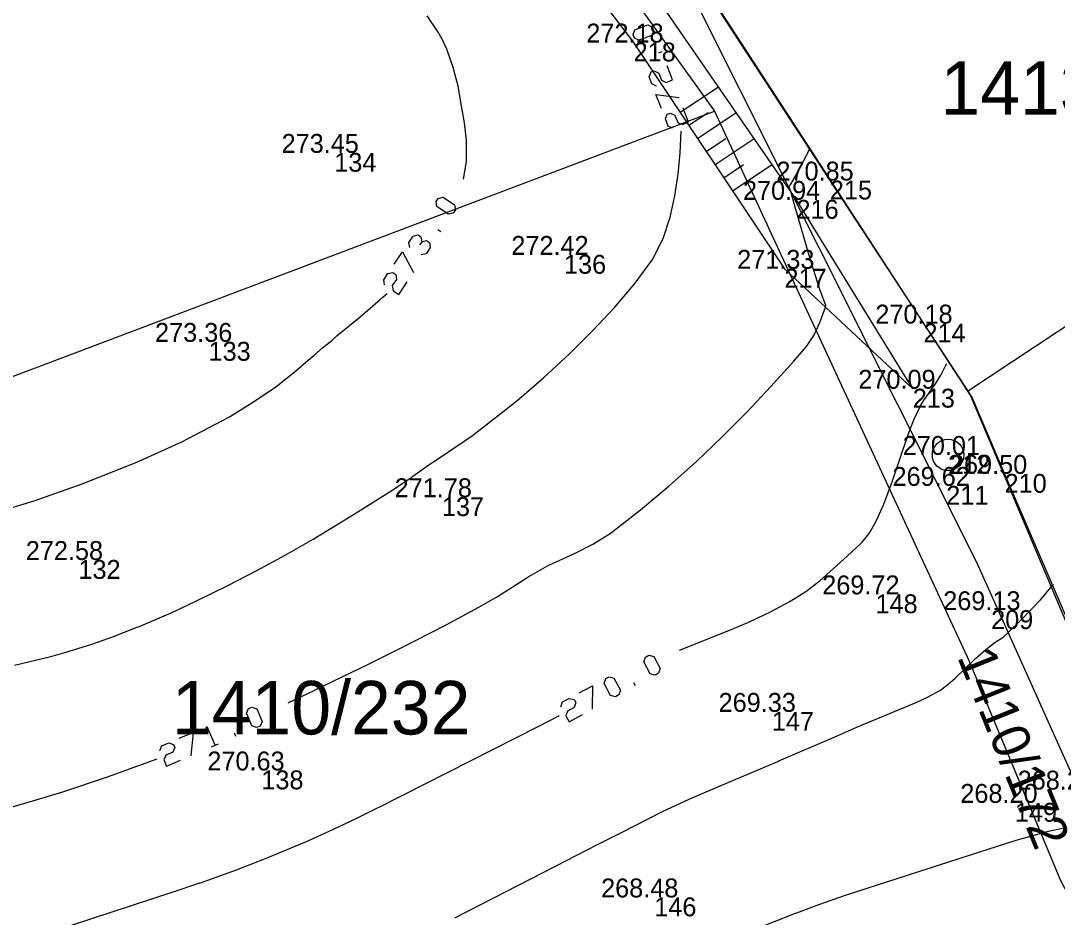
# Model space of a CAD drawing. Extents: x -771260 to -770828, y -1053564 to -1052811.
# Drawn here: x -770951.08 to -770918.15, y -1053293.16 to -1053264.67 of the extents above; entities that cross this region are included whole.
import ezdxf

# ---------------------------------------------------------------- set-up
doc = ezdxf.new("R2010")
doc.units = 0
for name, color, linetype in [('18_8_2023_plot', 7, 'Continuous'), ('18_8_2023_sachta', 7, 'Continuous'), ('18_8_2023_ter_hrana', 7, 'Continuous'), ('18_8_2023_ter_pata', 7, 'Continuous'), ('18_8_2023_ter_srafa', 7, 'Continuous'), ('18_8_2023_vrstevnice_po_1m', 7, 'Continuous'), ('18_8_2023_zamereny_bod', 7, 'Continuous'), ('18_8_2023_zamereny_bod_cislo', 7, 'Continuous'), ('18_8_2023_zamereny_bod_vyska', 7, 'Continuous'), ('DKM_Hranice parcel', 7, 'Continuous'), ('DKM_Parcelní čísla', 7, 'Continuous')]:
    doc.layers.add(name, color=color, linetype=linetype)

msp = doc.modelspace()

# ---------------------------------------------------------------- linework, layer by layer
at = {"layer": '18_8_2023_plot'}
for p, q in [((-770929.672, -1053263.164), (-770925.377, -1053269.752)), ((-770925.377, -1053269.752), (-770920.87, -1053276.639)), ((-770920.87, -1053276.639), (-770919.828, -1053279.071)), ((-770919.828, -1053279.071), (-770914.484, -1053291.532))]:
    msp.add_line(p, q, dxfattribs=at)
at = {"layer": '18_8_2023_sachta'}
msp.add_circle((-770921.622, -1053278.469), 0.5, dxfattribs=at)
at = {"layer": '18_8_2023_ter_hrana'}
for p, q in [((-770938.594, -1053256.22), (-770931.61, -1053265.367)), ((-770931.61, -1053265.367), (-770926.819, -1053272.556)), ((-770926.819, -1053272.556), (-770922.744, -1053276.366))]:
    msp.add_line(p, q, dxfattribs=at)
at = {"layer": '18_8_2023_ter_pata'}
for p, q in [((-770926.437, -1053270.365), (-770930.841, -1053263.982)), ((-770922.744, -1053276.366), (-770926.437, -1053270.365))]:
    msp.add_line(p, q, dxfattribs=at)
at = {"layer": '18_8_2023_ter_srafa'}
for p, q in [((-770930.134, -1053267.581), (-770928.917, -1053266.77)), ((-770929.856, -1053267.997), (-770929.244, -1053267.589)), ((-770929.579, -1053268.413), (-770928.349, -1053267.593)), ((-770929.302, -1053268.829), (-770928.683, -1053268.417)), ((-770929.025, -1053269.245), (-770927.781, -1053268.416)), ((-770928.747, -1053269.661), (-770928.122, -1053269.245)), ((-770928.47, -1053270.078), (-770927.213, -1053269.24))]:
    msp.add_line(p, q, dxfattribs=at)
at = {"layer": '18_8_2023_vrstevnice_po_1m'}
for points in [[(-770937.013, -1053269.71), (-770936.921, -1053269.144), (-770936.917, -1053268.488), (-770936.925, -1053268.37), (-770936.981, -1053267.919), (-770937.075, -1053267.382), (-770937.186, -1053266.751), (-770937.34, -1053266.158), (-770937.543, -1053265.582), (-770937.683, -1053265.278), (-770937.818, -1053265.034), (-770938.172, -1053264.514)], [(-770930.975, -1053264.991), (-770931.034, -1053265.142), (-770931.441, -1053265.297), (-770931.585, -1053265.224), (-770931.628, -1053265.113), (-770931.569, -1053264.962), (-770931.162, -1053264.806), (-770931.018, -1053264.879), (-770930.975, -1053264.991)], [(-770937.818, -1053265.034), (-770937.818, -1053265.034)], [(-770937.683, -1053265.278), (-770937.683, -1053265.278)], [(-770937.543, -1053265.582), (-770937.543, -1053265.582)], [(-770930.718, -1053265.662), (-770930.82, -1053265.701)], [(-770937.34, -1053266.158), (-770937.34, -1053266.158)], [(-770930.884, -1053266.751), (-770931.029, -1053266.678), (-770931.114, -1053266.454), (-770931.055, -1053266.303), (-770930.954, -1053266.265), (-770930.809, -1053266.337), (-770930.724, -1053266.561), (-770930.579, -1053266.634), (-770930.376, -1053266.556), (-770930.547, -1053266.109)], [(-770937.186, -1053266.751), (-770937.186, -1053266.751)], [(-770930.729, -1053267.46), (-770930.9, -1053267.013), (-770930.162, -1053267.115)], [(-770930.371, -1053268.092), (-770930.515, -1053268.019), (-770930.601, -1053267.796), (-770930.542, -1053267.645), (-770930.44, -1053267.606), (-770930.296, -1053267.679), (-770930.21, -1053267.903), (-770930.066, -1053267.976), (-770929.862, -1053267.898), (-770930.034, -1053267.451)], [(-770951.278, -1053285.145), (-770950.122, -1053284.874), (-770949.677, -1053284.747), (-770948.817, -1053284.481), (-770948.1, -1053284.224), (-770947.386, -1053283.946), (-770947.341, -1053283.929), (-770946.229, -1053283.45), (-770945.427, -1053283.075), (-770944.496, -1053282.619), (-770943.581, -1053282.143), (-770942.681, -1053281.652), (-770941.793, -1053281.144), (-770940.921, -1053280.62), (-770940.369, -1053280.273), (-770939.345, -1053279.631), (-770938.657, -1053279.174), (-770938.618, -1053279.147), (-770938.036, -1053278.734), (-770938.002, -1053278.71), (-770936.964, -1053278.013), (-770936.699, -1053277.827), (-770936.677, -1053277.811), (-770936.246, -1053277.486), (-770935.32, -1053276.75), (-770934.464, -1053276.01), (-770933.661, -1053275.266), (-770932.906, -1053274.52), (-770932.205, -1053273.77), (-770931.564, -1053273.016), (-770931.035, -1053272.289), (-770931.011, -1053272.256), (-770930.674, -1053271.589), (-770930.45, -1053270.915), (-770930.298, -1053270.236), (-770930.197, -1053269.553), (-770930.135, -1053268.869), (-770930.103, -1053268.182)], [(-770936.981, -1053267.919), (-770936.981, -1053267.919)], [(-770936.925, -1053268.37), (-770936.925, -1053268.37)], [(-770936.917, -1053268.488), (-770936.917, -1053268.488)], [(-770942.585, -1053286.346), (-770941.758, -1053285.955), (-770941.744, -1053285.948), (-770940.011, -1053285.109), (-770939.015, -1053284.612), (-770937.568, -1053283.867), (-770936.527, -1053283.309), (-770936.004, -1053283.008), (-770935.967, -1053282.987), (-770934.942, -1053282.332), (-770934.344, -1053281.995), (-770934.301, -1053281.971), (-770933.507, -1053281.607), (-770932.887, -1053281.298), (-770932.405, -1053280.999), (-770932.359, -1053280.97), (-770931.387, -1053280.218), (-770930.479, -1053279.452), (-770929.618, -1053278.676), (-770928.796, -1053277.89), (-770928.007, -1053277.098), (-770927.249, -1053276.298), (-770926.519, -1053275.492), (-770926.127, -1053275.032), (-770926.097, -1053274.997), (-770925.886, -1053274.674), (-770925.7, -1053274.263), (-770925.52, -1053273.771), (-770925.503, -1053273.725), (-770925.712, -1053273.148), (-770926.006, -1053272.235), (-770926.478, -1053270.598), (-770926.586, -1053270.221), (-770926.611, -1053270.134), (-770926.624, -1053270.093), (-770926.672, -1053269.947), (-770926.644, -1053269.905), (-770926.616, -1053269.865), (-770926.389, -1053269.463), (-770926.023, -1053268.761), (-770926, -1053268.717)], [(-770930.135, -1053268.869), (-770930.135, -1053268.869)], [(-770926, -1053268.717), (-770926, -1053268.717)], [(-770926, -1053268.717), (-770926, -1053268.717)], [(-770936.921, -1053269.144), (-770936.921, -1053269.144)], [(-770930.197, -1053269.553), (-770930.197, -1053269.553)], [(-770926.389, -1053269.463), (-770926.389, -1053269.463)], [(-770937.013, -1053269.71), (-770937.013, -1053269.71)], [(-770926.616, -1053269.865), (-770926.616, -1053269.865)], [(-770926.672, -1053269.947), (-770926.672, -1053269.947)], [(-770926.611, -1053270.134), (-770926.611, -1053270.134)], [(-770937.339, -1053270.784), (-770937.496, -1053270.823), (-770937.858, -1053270.581), (-770937.882, -1053270.421), (-770937.815, -1053270.322), (-770937.658, -1053270.283), (-770937.296, -1053270.525), (-770937.272, -1053270.685), (-770937.339, -1053270.784)], [(-770930.298, -1053270.236), (-770930.298, -1053270.236)], [(-770930.45, -1053270.915), (-770930.45, -1053270.915)], [(-770938.723, -1053271.875), (-770938.747, -1053271.715), (-770938.614, -1053271.516), (-770938.457, -1053271.477), (-770938.366, -1053271.538), (-770938.342, -1053271.698)], [(-770937.738, -1053271.382), (-770937.829, -1053271.321)], [(-770938.342, -1053271.698), (-770938.409, -1053271.797)], [(-770938.342, -1053271.698), (-770938.185, -1053271.659), (-770938.095, -1053271.719), (-770938.071, -1053271.879), (-770938.204, -1053272.078), (-770938.361, -1053272.117)], [(-770930.674, -1053271.589), (-770930.674, -1053271.589)], [(-770939.213, -1053272.412), (-770938.946, -1053272.014), (-770938.603, -1053272.675)], [(-770931.011, -1053272.256), (-770931.011, -1053272.256)], [(-770926.006, -1053272.235), (-770926.006, -1053272.235)], [(-770939.521, -1053273.07), (-770939.545, -1053272.91), (-770939.412, -1053272.71), (-770939.255, -1053272.671), (-770939.165, -1053272.732), (-770939.141, -1053272.892), (-770939.274, -1053273.091), (-770939.25, -1053273.251), (-770939.069, -1053273.372), (-770938.803, -1053272.974)], [(-770931.564, -1053273.016), (-770931.564, -1053273.016)], [(-770925.712, -1053273.148), (-770925.712, -1053273.148)], [(-770951.665, -1053280.24), (-770950.647, -1053279.926), (-770949.13, -1053279.385), (-770947.388, -1053278.695), (-770947.373, -1053278.689), (-770945.956, -1053278.05), (-770944.448, -1053277.257), (-770943.648, -1053276.766), (-770942.969, -1053276.303), (-770942.929, -1053276.276), (-770942.342, -1053275.801), (-770941.952, -1053275.463), (-770941.771, -1053275.315), (-770941.489, -1053275.068), (-770941.197, -1053274.831), (-770941.024, -1053274.678), (-770940.293, -1053274.078), (-770939.664, -1053273.526), (-770939.632, -1053273.498), (-770939.44, -1053273.34)], [(-770939.632, -1053273.498), (-770939.632, -1053273.498)], [(-770932.205, -1053273.77), (-770932.205, -1053273.77)], [(-770925.503, -1053273.725), (-770925.503, -1053273.725)], [(-770940.293, -1053274.078), (-770940.293, -1053274.078)], [(-770925.7, -1053274.263), (-770925.7, -1053274.263)], [(-770941.024, -1053274.678), (-770941.024, -1053274.678)], [(-770932.906, -1053274.52), (-770932.906, -1053274.52)], [(-770925.886, -1053274.674), (-770925.886, -1053274.674)], [(-770941.489, -1053275.068), (-770941.489, -1053275.068)], [(-770941.197, -1053274.831), (-770941.197, -1053274.831)], [(-770926.097, -1053274.997), (-770926.097, -1053274.997)], [(-770941.952, -1053275.463), (-770941.952, -1053275.463)], [(-770941.771, -1053275.315), (-770941.771, -1053275.315)], [(-770933.661, -1053275.266), (-770933.661, -1053275.266)], [(-770942.342, -1053275.801), (-770942.342, -1053275.801)], [(-770930.149, -1053284.673), (-770928.475, -1053284), (-770927.904, -1053283.757), (-770927.259, -1053283.454), (-770926.668, -1053283.139), (-770926.142, -1053282.81), (-770925.732, -1053282.495), (-770925.692, -1053282.464), (-770924.832, -1053281.687), (-770924.383, -1053281.271), (-770924.351, -1053281.241), (-770924.127, -1053280.966), (-770923.903, -1053280.569), (-770923.662, -1053280.03), (-770923.39, -1053279.295), (-770923.144, -1053278.571), (-770922.888, -1053277.82), (-770922.706, -1053277.349), (-770922.533, -1053276.976), (-770922.509, -1053276.923), (-770922.381, -1053276.722), (-770922.373, -1053276.711), (-770922.02, -1053276.207), (-770921.852, -1053275.94), (-770921.689, -1053275.621), (-770921.666, -1053275.575)], [(-770926.519, -1053275.492), (-770926.519, -1053275.492)], [(-770921.666, -1053275.575), (-770921.666, -1053275.575)], [(-770921.666, -1053275.575), (-770921.666, -1053275.575)], [(-770934.464, -1053276.01), (-770934.464, -1053276.01)], [(-770921.852, -1053275.94), (-770921.852, -1053275.94)], [(-770942.929, -1053276.276), (-770942.929, -1053276.276)], [(-770927.249, -1053276.298), (-770927.249, -1053276.298)], [(-770922.02, -1053276.207), (-770922.02, -1053276.207)], [(-770943.648, -1053276.766), (-770943.648, -1053276.766)], [(-770935.32, -1053276.75), (-770935.32, -1053276.75)], [(-770922.381, -1053276.722), (-770922.381, -1053276.722)], [(-770928.007, -1053277.098), (-770928.007, -1053277.098)], [(-770922.509, -1053276.923), (-770922.509, -1053276.923)], [(-770944.448, -1053277.257), (-770944.448, -1053277.257)], [(-770922.706, -1053277.349), (-770922.706, -1053277.349)], [(-770936.246, -1053277.486), (-770936.246, -1053277.486)], [(-770945.956, -1053278.05), (-770945.956, -1053278.05)], [(-770936.964, -1053278.013), (-770936.964, -1053278.013)], [(-770936.677, -1053277.811), (-770936.677, -1053277.811)], [(-770928.796, -1053277.89), (-770928.796, -1053277.89)], [(-770922.888, -1053277.82), (-770922.888, -1053277.82)], [(-770947.373, -1053278.689), (-770947.373, -1053278.689)], [(-770938.002, -1053278.71), (-770938.002, -1053278.71)], [(-770929.618, -1053278.676), (-770929.618, -1053278.676)], [(-770949.13, -1053279.385), (-770949.13, -1053279.385)], [(-770938.618, -1053279.147), (-770938.618, -1053279.147)], [(-770923.39, -1053279.295), (-770923.39, -1053279.295)], [(-770939.345, -1053279.631), (-770939.345, -1053279.631)], [(-770930.479, -1053279.452), (-770930.479, -1053279.452)], [(-770950.647, -1053279.926), (-770950.647, -1053279.926)], [(-770923.662, -1053280.03), (-770923.662, -1053280.03)], [(-770931.387, -1053280.218), (-770931.387, -1053280.218)], [(-770940.921, -1053280.62), (-770940.921, -1053280.62)], [(-770923.903, -1053280.569), (-770923.903, -1053280.569)], [(-770932.359, -1053280.97), (-770932.359, -1053280.97)], [(-770924.127, -1053280.966), (-770924.127, -1053280.966)], [(-770941.793, -1053281.144), (-770941.793, -1053281.144)], [(-770932.887, -1053281.298), (-770932.887, -1053281.298)], [(-770924.351, -1053281.241), (-770924.351, -1053281.241)], [(-770942.681, -1053281.652), (-770942.681, -1053281.652)], [(-770933.507, -1053281.607), (-770933.507, -1053281.607)], [(-770924.832, -1053281.687), (-770924.832, -1053281.687)], [(-770934.301, -1053281.971), (-770934.301, -1053281.971)], [(-770943.581, -1053282.143), (-770943.581, -1053282.143)], [(-770934.942, -1053282.332), (-770934.942, -1053282.332)], [(-770944.496, -1053282.619), (-770944.496, -1053282.619)], [(-770937.285, -1053293.181), (-770934.067, -1053291.521), (-770932.761, -1053290.847), (-770932.037, -1053290.488), (-770931.999, -1053290.469), (-770930.698, -1053289.802), (-770929.821, -1053289.4), (-770928.658, -1053288.901), (-770927.034, -1053288.205), (-770927.001, -1053288.191), (-770925.17, -1053287.4), (-770924.5, -1053287.11), (-770922.618, -1053286.325), (-770922.272, -1053286.164), (-770921.888, -1053285.952), (-770921.849, -1053285.931), (-770921.625, -1053285.768), (-770921.398, -1053285.566), (-770920.753, -1053284.942), (-770920.427, -1053284.652), (-770920.13, -1053284.419), (-770920.098, -1053284.394), (-770919.992, -1053284.334), (-770919.876, -1053284.256), (-770919.841, -1053284.232), (-770919.736, -1053284.132), (-770919.286, -1053283.703), (-770918.687, -1053283.069), (-770918.305, -1053282.622), (-770918.275, -1053282.586)], [(-770925.692, -1053282.464), (-770925.692, -1053282.464)], [(-770935.967, -1053282.987), (-770935.967, -1053282.987)], [(-770926.142, -1053282.81), (-770926.142, -1053282.81)], [(-770945.427, -1053283.075), (-770945.427, -1053283.075)], [(-770936.527, -1053283.309), (-770936.527, -1053283.309)], [(-770926.668, -1053283.139), (-770926.668, -1053283.139)], [(-770918.687, -1053283.069), (-770918.687, -1053283.069)], [(-770946.229, -1053283.45), (-770946.229, -1053283.45)], [(-770927.259, -1053283.454), (-770927.259, -1053283.454)], [(-770919.286, -1053283.703), (-770919.286, -1053283.703)], [(-770947.341, -1053283.929), (-770947.341, -1053283.929)], [(-770937.568, -1053283.867), (-770937.568, -1053283.867)], [(-770928.475, -1053284), (-770928.475, -1053284)], [(-770927.904, -1053283.757), (-770927.904, -1053283.757)], [(-770948.1, -1053284.224), (-770948.1, -1053284.224)], [(-770919.992, -1053284.334), (-770919.992, -1053284.334)], [(-770919.841, -1053284.232), (-770919.841, -1053284.232)], [(-770948.817, -1053284.481), (-770948.817, -1053284.481)], [(-770939.015, -1053284.612), (-770939.015, -1053284.612)], [(-770930.149, -1053284.673), (-770930.149, -1053284.673)], [(-770920.427, -1053284.652), (-770920.427, -1053284.652)], [(-770920.098, -1053284.394), (-770920.098, -1053284.394)], [(-770950.122, -1053284.874), (-770950.122, -1053284.874)], [(-770949.677, -1053284.747), (-770949.677, -1053284.747)], [(-770930.923, -1053285.465), (-770931.08, -1053285.426), (-770931.287, -1053285.043), (-770931.234, -1053284.891), (-770931.129, -1053284.833), (-770930.972, -1053284.872), (-770930.764, -1053285.255), (-770930.818, -1053285.407), (-770930.923, -1053285.465)], [(-770920.753, -1053284.942), (-770920.753, -1053284.942)], [(-770940.011, -1053285.109), (-770940.011, -1053285.109)], [(-770932.185, -1053286.15), (-770932.343, -1053286.111), (-770932.55, -1053285.728), (-770932.497, -1053285.576), (-770932.392, -1053285.519), (-770932.235, -1053285.557), (-770932.027, -1053285.94), (-770932.08, -1053286.093), (-770932.185, -1053286.15)], [(-770921.398, -1053285.566), (-770921.398, -1053285.566)], [(-770941.744, -1053285.948), (-770941.744, -1053285.948)], [(-770933.339, -1053286.032), (-770932.918, -1053285.804), (-770932.922, -1053286.549)], [(-770931.554, -1053285.807), (-770931.606, -1053285.711)], [(-770921.849, -1053285.931), (-770921.849, -1053285.931)], [(-770921.625, -1053285.768), (-770921.625, -1053285.768)], [(-770942.585, -1053286.346), (-770942.585, -1053286.346)], [(-770933.918, -1053286.471), (-770933.865, -1053286.318), (-770933.654, -1053286.204), (-770933.497, -1053286.242), (-770933.445, -1053286.338), (-770933.499, -1053286.491), (-770933.709, -1053286.605), (-770933.762, -1053286.758), (-770933.659, -1053286.949), (-770933.238, -1053286.72)], [(-770922.618, -1053286.325), (-770922.618, -1053286.325)], [(-770922.272, -1053286.164), (-770922.272, -1053286.164)], [(-770943.585, -1053287.13), (-770943.738, -1053287.077), (-770943.91, -1053286.677), (-770943.843, -1053286.53), (-770943.733, -1053286.483), (-770943.58, -1053286.536), (-770943.408, -1053286.936), (-770943.475, -1053287.083), (-770943.585, -1053287.13)], [(-770949.459, -1053293.412), (-770946.265, -1053292.365), (-770945.385, -1053292.064), (-770945.369, -1053292.059), (-770944.225, -1053291.646), (-770943.298, -1053291.289), (-770941.929, -1053290.718), (-770941.888, -1053290.701), (-770941.141, -1053290.364), (-770940.404, -1053290.012), (-770939.745, -1053289.686), (-770939.693, -1053289.66), (-770934.618, -1053287.086), (-770934.01, -1053286.767), (-770933.972, -1053286.748)], [(-770946.043, -1053287.473), (-770945.603, -1053287.285), (-770945.676, -1053288.026)], [(-770945.23, -1053287.243), (-770945.163, -1053287.096), (-770944.906, -1053287.696)], [(-770944.246, -1053287.413), (-770944.289, -1053287.313)], [(-770934.618, -1053287.086), (-770934.618, -1053287.086)], [(-770924.5, -1053287.11), (-770924.5, -1053287.11)], [(-770946.661, -1053287.856), (-770946.594, -1053287.709), (-770946.374, -1053287.615), (-770946.221, -1053287.668), (-770946.178, -1053287.768), (-770946.245, -1053287.915), (-770946.465, -1053288.009), (-770946.532, -1053288.157), (-770946.446, -1053288.357), (-770946.006, -1053288.168)], [(-770945.016, -1053287.743), (-770944.796, -1053287.649)], [(-770970.288, -1053291.973), (-770969.141, -1053292.132), (-770969.13, -1053292.133), (-770967.843, -1053292.237), (-770966.508, -1053292.257), (-770965.559, -1053292.22), (-770965.125, -1053292.194), (-770964.516, -1053292.138), (-770963.589, -1053292.027), (-770963.524, -1053292.019), (-770962.187, -1053291.813), (-770959.915, -1053291.424), (-770955.186, -1053290.57), (-770954.529, -1053290.445), (-770954.516, -1053290.443), (-770953.213, -1053290.168), (-770952.376, -1053289.953), (-770952.329, -1053289.94), (-770950.693, -1053289.464), (-770949.741, -1053289.168), (-770948.292, -1053288.685), (-770947.97, -1053288.569), (-770946.74, -1053288.127)], [(-770927.001, -1053288.191), (-770927.001, -1053288.191)], [(-770948.292, -1053288.685), (-770948.292, -1053288.685)], [(-770949.741, -1053289.168), (-770949.741, -1053289.168)], [(-770950.693, -1053289.464), (-770950.693, -1053289.464)], [(-770929.821, -1053289.4), (-770929.821, -1053289.4)], [(-770939.693, -1053289.66), (-770939.693, -1053289.66)], [(-770930.698, -1053289.802), (-770930.698, -1053289.802)], [(-770940.404, -1053290.012), (-770940.404, -1053290.012)], [(-770941.141, -1053290.364), (-770941.141, -1053290.364)], [(-770931.999, -1053290.469), (-770931.999, -1053290.469)], [(-770927.644, -1053293.489), (-770926.464, -1053293.029), (-770926.43, -1053293.016), (-770925.724, -1053292.751), (-770924.844, -1053292.449), (-770920.941, -1053291.19), (-770919.458, -1053290.711), (-770918.843, -1053290.54), (-770918.437, -1053290.427), (-770917.987, -1053290.331)], [(-770918.437, -1053290.427), (-770918.437, -1053290.427)], [(-770941.888, -1053290.701), (-770941.888, -1053290.701)], [(-770932.761, -1053290.847), (-770932.761, -1053290.847)], [(-770919.458, -1053290.711), (-770919.458, -1053290.711)], [(-770943.298, -1053291.289), (-770943.298, -1053291.289)], [(-770944.225, -1053291.646), (-770944.225, -1053291.646)], [(-770945.369, -1053292.059), (-770945.369, -1053292.059)], [(-770946.265, -1053292.365), (-770946.265, -1053292.365)], [(-770924.844, -1053292.449), (-770924.844, -1053292.449)], [(-770925.724, -1053292.751), (-770925.724, -1053292.751)], [(-770926.43, -1053293.016), (-770926.43, -1053293.016)]]:
    msp.add_lwpolyline(points, dxfattribs=at)
at = {"layer": '18_8_2023_zamereny_bod'}
for p, q in [((-770931.61, -1053265.367), (-770931.61, -1053265.367)), ((-770941.119, -1053268.872), (-770941.119, -1053268.872)), ((-770925.377, -1053269.752), (-770925.377, -1053269.752)), ((-770926.437, -1053270.365), (-770926.437, -1053270.365)), ((-770933.822, -1053272.113), (-770933.822, -1053272.113)), ((-770926.819, -1053272.556), (-770926.819, -1053272.556)), ((-770922.404, -1053274.296), (-770922.404, -1053274.296)), ((-770945.111, -1053274.877), (-770945.111, -1053274.877)), ((-770922.744, -1053276.366), (-770922.744, -1053276.366)), ((-770921.622, -1053278.469), (-770921.622, -1053278.469)), ((-770919.828, -1053279.071), (-770919.828, -1053279.071)), ((-770921.678, -1053279.452), (-770921.678, -1053279.452)), ((-770937.699, -1053279.812), (-770937.699, -1053279.812)), ((-770949.244, -1053281.807), (-770949.244, -1053281.807)), ((-770923.928, -1053282.899), (-770923.928, -1053282.899)), ((-770920.255, -1053283.401), (-770920.255, -1053283.401)), ((-770927.22, -1053286.632), (-770927.22, -1053286.632)), ((-770943.435, -1053288.493), (-770943.435, -1053288.493)), ((-770919.502, -1053289.523), (-770919.502, -1053289.523)), ((-770930.955, -1053292.527), (-770930.955, -1053292.527))]:
    msp.add_line(p, q, dxfattribs=at)
at = {"layer": 'DKM_Hranice parcel'}
msp.add_line((-770921.01, -1053276.44), (-770907.55, -1053267.55), dxfattribs=at)
for points in [[(-770942.88, -1053251.43), (-770931.86, -1053263.62), (-770929.04, -1053267.55)], [(-770909.23, -1053307.52), (-770910.75, -1053304.08), (-770920.71, -1053281.89), (-770930.72, -1053261.88)], [(-770929.73, -1053263.03), (-770929.66, -1053263.13), (-770921.01, -1053276.44)], [(-770975.67, -1053281.73), (-770951.96, -1053276.21), (-770929.04, -1053267.55)], [(-770929.04, -1053267.55), (-770920.95, -1053285.02), (-770918.05, -1053291.99), (-770911.86, -1053303.41)], [(-770921.01, -1053276.44), (-770920.9, -1053276.61), (-770914.65, -1053291.42)]]:
    msp.add_lwpolyline(points, dxfattribs=at)

# ---------------------------------------------------------------- texts
at = {"layer": '18_8_2023_zamereny_bod_cislo'}
for s, p in [('218', (-770931.61, -1053265.967)), ('134', (-770941.119, -1053269.472)), ('215', (-770925.377, -1053270.352)), ('216', (-770926.437, -1053270.965)), ('136', (-770933.822, -1053272.713)), ('217', (-770926.819, -1053273.156)), ('214', (-770922.404, -1053274.896)), ('133', (-770945.111, -1053275.477)), ('213', (-770922.744, -1053276.966)), ('212', (-770921.622, -1053279.069)), ('210', (-770919.828, -1053279.671)), ('211', (-770921.678, -1053280.052)), ('137', (-770937.699, -1053280.412)), ('132', (-770949.244, -1053282.407)), ('148', (-770923.928, -1053283.499)), ('209', (-770920.255, -1053284.001)), ('147', (-770927.22, -1053287.232)), ('138', (-770943.435, -1053289.093)), ('149', (-770919.502, -1053290.123)), ('146', (-770930.955, -1053293.127))]:
    msp.add_text(s, height=0.6, dxfattribs=at).set_placement(p)
at = {"layer": '18_8_2023_zamereny_bod_vyska'}
for s, p in [('272.18 ', (-770933.112, -1053265.367)), ('273.45 ', (-770942.791, -1053268.872)), ('270.85 ', (-770927.075, -1053269.752)), ('270.94 ', (-770928.137, -1053270.365)), ('272.42 ', (-770935.494, -1053272.113)), ('271.33 ', (-770928.321, -1053272.556)), ('270.18 ', (-770923.932, -1053274.296)), ('273.36 ', (-770946.811, -1053274.877)), ('270.09 ', (-770924.472, -1053276.366)), ('270.01 ', (-770923.062, -1053278.469)), ('269.50 ', (-770921.562, -1053279.071)), ('269.62 ', (-770923.386, -1053279.452)), ('271.78 ', (-770939.201, -1053279.812)), ('272.58 ', (-770950.916, -1053281.807)), ('269.72 ', (-770925.619, -1053282.899)), ('269.13 ', (-770921.776, -1053283.401)), ('269.33 ', (-770928.911, -1053286.632)), ('270.63 ', (-770945.149, -1053288.493)), ('268.25 ', (-770919.413, -1053289.101)), ('268.20 ', (-770921.234, -1053289.523)), ('268.48 ', (-770932.643, -1053292.527))]:
    msp.add_text(s, height=0.6, dxfattribs=at).set_placement(p)
at = {"layer": 'DKM_Parcelní čísla'}
for s, p in [('1413/288', (-770921.865, -1053267.66)), ('1410/232', (-770946.275, -1053287.35))]:
    msp.add_text(s, height=1.7, dxfattribs=at).set_placement(p)
msp.add_text('1410/172', height=1.2, rotation=292, dxfattribs=at).set_placement((-770921.343, -1053284.881))

doc.saveas('drawing.dxf')
